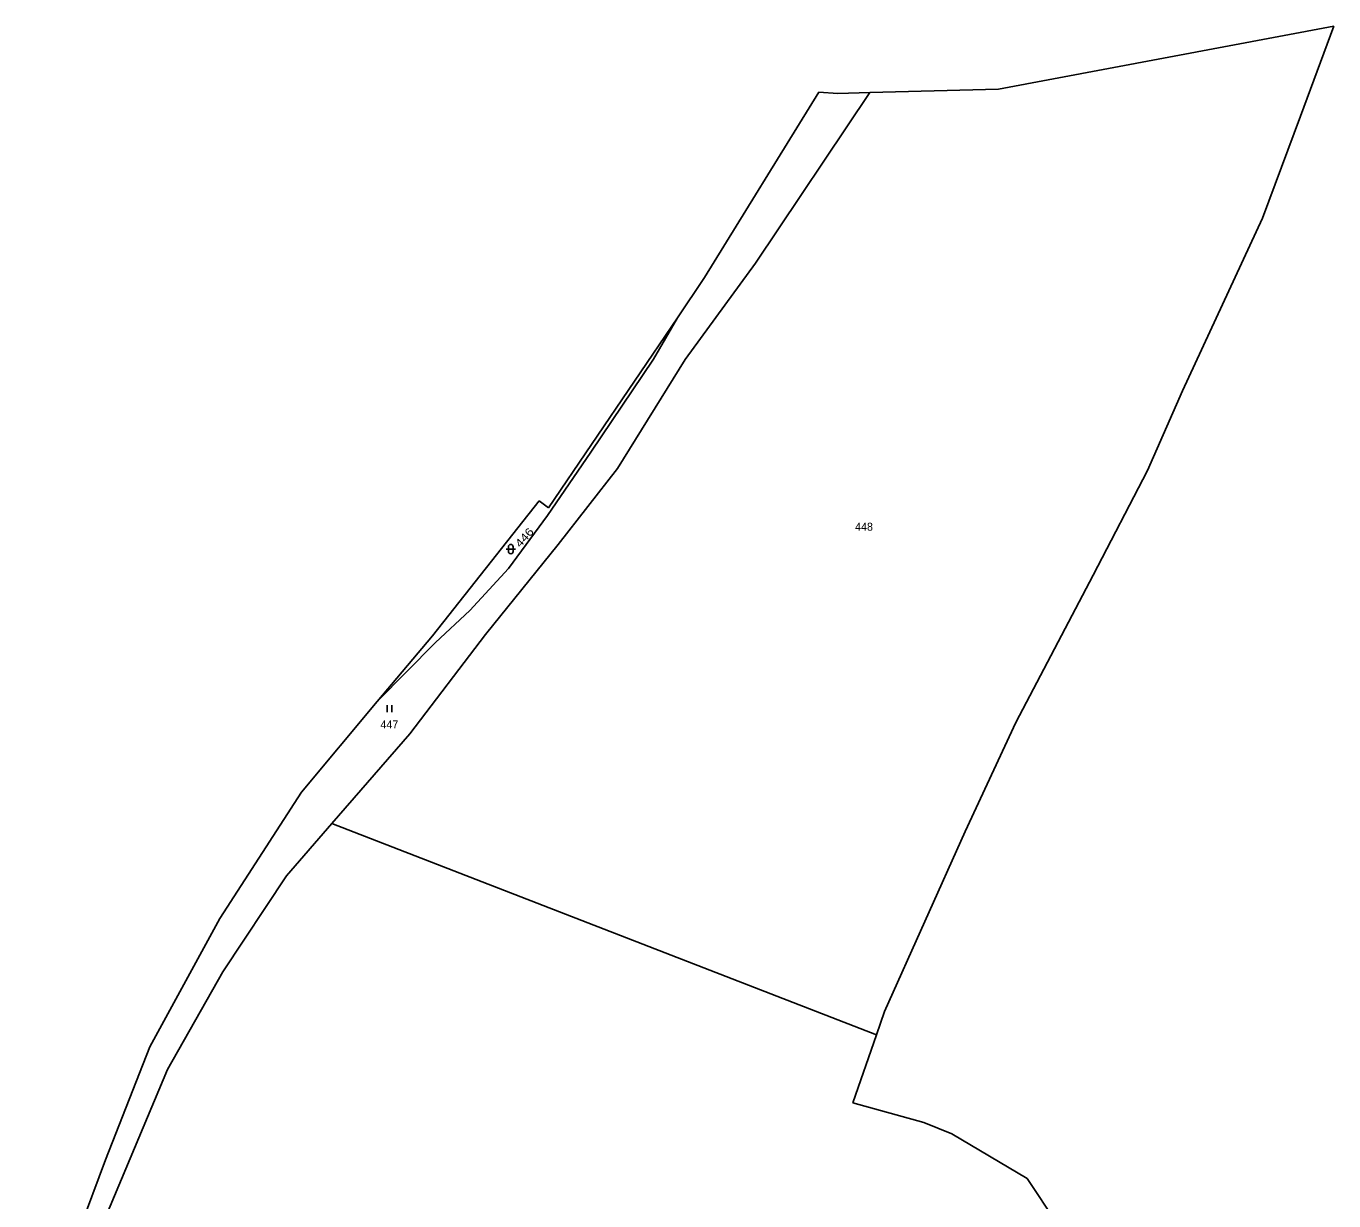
# Model space of a CAD drawing. Extents: x -769392 to -767038, y -1018329 to -1015269.
# Drawn here: x -768026.2 to -767748.5, y -1015518.7 to -1015269.2 of the extents above; entities that cross this region are included whole.
import ezdxf

# ---------------------------------------------------------------- set-up
doc = ezdxf.new("R2010")
doc.units = 0
doc.header["$LTSCALE"] = 0.68
doc.layers.add('1', color=7, linetype='Continuous', lineweight=25)
doc.layers.add('3', color=7, linetype='Continuous', lineweight=25)
doc.layers.add('2', color=7, linetype='Continuous')

msp = doc.modelspace()

# ---------------------------------------------------------------- linework, layer by layer
at = {"layer": '1'}
for p, q in [((-767819.67, -1015282.57), (-767748.47, -1015269.2)), ((-767748.47, -1015269.2), (-767755.55, -1015288.31)), ((-767846.99, -1015283.29), (-767819.67, -1015282.57)), ((-767882.1, -1015322.59), (-767857.84, -1015283.25)), ((-767857.84, -1015283.25), (-767853.8, -1015283.47)), ((-767853.8, -1015283.47), (-767846.99, -1015283.29)), ((-767755.55, -1015288.31), (-767763.6, -1015309.97)), ((-767763.6, -1015309.97), (-767780.6, -1015346.65)), ((-767887.89, -1015331.13), (-767882.1, -1015322.59)), ((-767915.24, -1015371.49), (-767887.89, -1015331.13)), ((-767780.6, -1015346.65), (-767788.04, -1015363.57)), ((-767788.04, -1015363.57), (-767799.55, -1015385.77)), ((-767917.26, -1015370.01), (-767939.91, -1015398.65)), ((-767915.24, -1015371.49), (-767917.26, -1015370.01)), ((-767799.55, -1015385.77), (-767816.03, -1015417.1)), ((-767951.62, -1015412.64), (-767939.91, -1015398.65)), ((-767967.72, -1015431.89), (-767951.62, -1015412.64)), ((-767816.03, -1015417.1), (-767826.78, -1015440.2)), ((-767985.03, -1015458.68), (-767967.72, -1015431.89)), ((-767961.24, -1015438.53), (-767845.62, -1015483.42)), ((-767826.78, -1015440.2), (-767843.89, -1015478.43)), ((-767999.95, -1015485.95), (-767985.03, -1015458.68)), ((-767843.89, -1015478.43), (-767845.62, -1015483.42)), ((-767845.62, -1015483.42), (-767850.6, -1015497.83)), ((-768009.31, -1015509.93), (-767999.95, -1015485.95)), ((-767850.6, -1015497.83), (-767835.54, -1015502.04)), ((-767835.54, -1015502.04), (-767829.6, -1015504.41)), ((-767829.6, -1015504.41), (-767813.62, -1015513.94)), ((-768009.31, -1015509.93), (-768016.5, -1015529.16)), ((-767813.62, -1015513.94), (-767807.32, -1015523.38))]:
    msp.add_line(p, q, dxfattribs=at)
for points in [[(-767961.24, -1015438.53), (-767944.69, -1015419.51), (-767928.6, -1015398.37), (-767913.21, -1015379.3), (-767900.58, -1015363.16), (-767886.26, -1015339.97), (-767871.26, -1015319.52), (-767846.99, -1015283.29)], [(-767887.89, -1015331.13), (-767892.95, -1015339.9), (-767906.24, -1015359.68), (-767915.44, -1015373.13), (-767923.77, -1015384.34), (-767931.93, -1015393.3), (-767939.28, -1015400.1), (-767951.62, -1015412.64)], [(-768026.18, -1015579.73), (-768015.46, -1015541.3), (-768009.26, -1015521.99), (-767996.16, -1015490.74), (-767984.44, -1015470.06), (-767970.88, -1015449.61), (-767961.24, -1015438.53)]]:
    msp.add_lwpolyline(points, dxfattribs=at)
at = {"layer": '3'}
for p, q in [((-767923.761, -1015379.761), (-767923.761, -1015380.762)), ((-767922.759, -1015380.762), (-767922.759, -1015379.761)), ((-767924.261, -1015380.261), (-767922.259, -1015380.261)), ((-767949.501, -1015414.91), (-767949.501, -1015413.41)), ((-767948.5, -1015414.91), (-767948.5, -1015413.41))]:
    msp.add_line(p, q, dxfattribs=at)
for centre, start, end in [((-767923.26, -1015379.7609), 0, 180), ((-767923.26, -1015380.7609), 180, 359.98789)]:
    msp.add_arc(centre, 0.5, start, end, dxfattribs=at)

# ---------------------------------------------------------------- texts
at = {"layer": '2', "width": 1.2}
msp.add_text('446', height=1.7, rotation=48, dxfattribs=at).set_placement((-767921.264, -1015380.044))
at = {"layer": '2'}
for s, p in [('448', (-767850.14, -1015376.345)), ('447', (-767950.94, -1015418.345))]:
    msp.add_text(s, height=1.7, dxfattribs=at).set_placement(p)

doc.saveas('drawing.dxf')
